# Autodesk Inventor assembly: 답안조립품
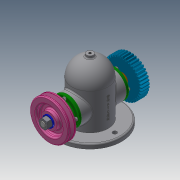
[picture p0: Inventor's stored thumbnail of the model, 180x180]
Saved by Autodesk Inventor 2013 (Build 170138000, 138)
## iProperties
Created: 2019-11
Part Number: 답안조립품
Document SubType Name: Assembly
Designer: 19
Author: 19
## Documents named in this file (14)
- C:\Users\user\Desktop\491104v1030\답안조립품.iam
- C:\Users\user\Desktop\491104v1030\본체.ipt
- C:\Users\user\Desktop\491104v1030\V-벨트풀리.ipt
- V-벨트풀리.ipt
- C:\Users\user\Desktop\491104v1030\너트 M12x1.25.ipt
- C:\Users\user\Desktop\491104v1030\베어링 6203.ipt
- C:\Users\user\Desktop\491104v1030\볼트 M4.ipt
- C:\Users\user\Desktop\491104v1030\부시.ipt
- C:\Users\user\Desktop\491104v1030\스퍼기어.ipt
- C:\Users\user\Desktop\491104v1030\오일 실 26 38 8.ipt
- C:\Users\user\Desktop\491104v1030\와셔 12x24.ipt
- C:\Users\user\Desktop\491104v1030\축.ipt
- C:\Users\user\Desktop\491104v1030\커버.ipt
- C:\Users\user\Desktop\491104v1030\키 5x5x12.ipt
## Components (1 placed, 1 different names)
1. V-벨트풀리:1
